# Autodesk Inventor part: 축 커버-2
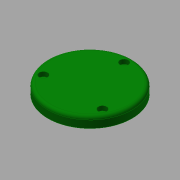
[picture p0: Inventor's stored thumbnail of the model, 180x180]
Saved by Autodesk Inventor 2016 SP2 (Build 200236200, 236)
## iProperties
Created: 2015-10
Part Number: 축 커버-2
Document SubType Name: Modeling
Designer: mdu
Density: 7.86 g/cm^3
Material: 강철, 연강
Appearance: 진녹색
Mass: 405.676 g
Surface Area: 133.169 cm^2
Volume: 51.6127 cm^3
Author: mdu
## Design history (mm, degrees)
sketch "스케치1"
  geometry: C1 r 40 at (0, 0) reference; C2 r 26 at (0, 0) reference; 1 further point
  node "참조1"
  node "참조2"
extrude "돌출1" new body sketch "스케치1" distance "d0" = 10; taper "d1" = 0 deg
extrude "돌출2" join sketch "스케치1" distance "d2" = 3; taper "d3" = 0 deg
sketch "스케치2"
  geometry: C1 r 20 at (0, 0); 1 further point
  constraints: 1 centre point, 1 coincident
  dimensions: "d13" = 40 diameter of C1
extrude "돌출3" cut sketch "스케치2" distance "d14" = 3; taper "d15" = 0 deg
sketch "스케치3"
  geometry: C1 r 1.621 at (0, 32.5) reference; 1 further point
hole "구멍2" sketch "스케치3" at (0, 32.5) diameter "d16" = 4.5; stored, may be unused: countersink angle "d20" = 90 deg, drill point angle "d22" = 118 deg; dims "d17" = 6, "d18" = 8, "d19" = 4.4, "d21" = 8
fillet "모깎기1" dims "d26" = 3, "d27" = 0.3
chamfer "모따기1" distance "d28" = 1; stored, may be unused: second distance "d29" = 2, angle "d30" = 45 deg
node "솔리드1"
pattern_circular "원형 패턴1" dims angle "d24" = 360 deg
node "참조3"
